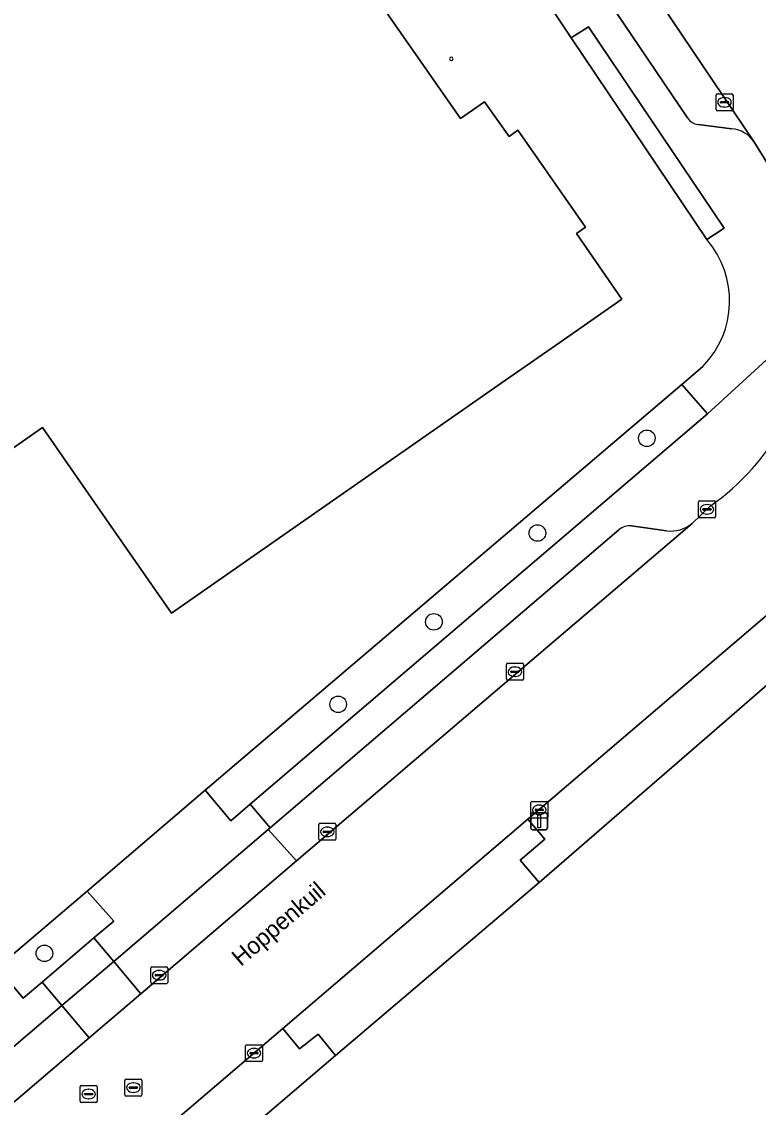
# Model space of a CAD drawing. Extents: x 156702 to 158052, y 387630 to 388992.
# Drawn here: x 157369.7 to 157413.2, y 387923.6 to 387987.6 of the extents above; entities that cross this region are included whole.
import ezdxf

# ---------------------------------------------------------------- set-up
doc = ezdxf.new("R2010")
doc.units = 0
for name, color, linetype in [('IMGEO_Boom', 7, 'Continuous'), ('IMGEO_Erf', 7, 'Continuous'), ('IMGEO_Groenvoorziening', 7, 'Continuous'), ('IMGEO_Kolk', 7, 'Continuous'), ('IMGEO_Lichtmast', 7, 'Continuous'), ('IMGEO_Openbare_ruimte_label', 7, 'Continuous'), ('IMGEO_Pand', 7, 'Continuous'), ('IMGEO_Parkeervlak_open', 7, 'Continuous'), ('IMGEO_Rijbaan_lokaal_gesloten', 7, 'Continuous'), ('IMGEO_Rijbaan_lokaal_open', 7, 'Continuous'), ('IMGEO_Rioolput', 7, 'Continuous'), ('IMGEO_Voetpad_open', 7, 'Continuous')]:
    doc.layers.add(name, color=color, linetype=linetype)

msp = doc.modelspace()

# ---------------------------------------------------------------- linework, layer by layer
at = {"layer": 'IMGEO_Boom'}
for centre in [(157406.636, 387963.06), (157400.18, 387957.47), (157394.069, 387952.231), (157388.42, 387947.363), (157371.085, 387932.67)]:
    msp.add_circle(centre, 0.489, dxfattribs=at)
at = {"layer": 'IMGEO_Erf'}
for points in [[(157387.19, 388039.182), (157396.502, 388024.511), (157402.741, 388015.343), (157403.363, 388015.762), (157413.667, 388000.525), (157419.496, 387991.988), (157429.376, 387977.195), (157434.667, 387969.272), (157436.067, 387967.176), (157433.406, 387964.883), (157433.59, 387964.667), (157433.73, 387964.762), (157434.042, 387964.343), (157428.255, 387959.385), (157427.905, 387959.765), (157428.127, 387959.953), (157427.939, 387960.171), (157427.645, 387960.512), (157423.765, 387957.199), (157400.278, 387936.844), (157388.261, 387926.646), (157368.779, 387910.004)], [(157410.18, 387974.784), (157402.177, 387986.679), (157401.025, 387988.392), (157393.215, 388000), (157371.506, 388032.159), (157369.928, 388034.292)], [(157368.332, 388003.627), (157376.541, 388009.329), (157383.04, 388000), (157393.139, 387985.505), (157395.632, 387981.926), (157397.057, 387982.917), (157398.504, 387980.872), (157399.026, 387981.234), (157403.012, 387975.51), (157402.494, 387975.151), (157405.159, 387971.263), (157401.506, 387968.719), (157398.499, 387966.625), (157378.578, 387952.75), (157377.05, 387954.95), (157374.897, 387958.052), (157370.981, 387963.692), (157367.677, 387961.4)], [(157380.576, 387942.295), (157408.698, 387966.241), (157409.937, 387967.305)], [(157342.068, 387909.735), (157348.404, 387915.137), (157358.974, 387923.885), (157368.291, 387931.841), (157373.604, 387936.342), (157380.576, 387942.295)]]:
    msp.add_lwpolyline(points, dxfattribs=at)
for centre, radius, start, end in [((157395.099, 387985.449), 0.1, 90, 270), ((157395.099, 387985.449), 0.1, 270, 90), ((157406.013, 387971.176), 5.512, 315.39208, 40.88604)]:
    msp.add_arc(centre, radius, start, end, dxfattribs=at)
at = {"layer": 'IMGEO_Groenvoorziening'}
for points in [[(157403.198, 387987.328), (157402.177, 387986.679), (157410.18, 387974.784), (157411.206, 387975.464)], [(157383.237, 387941.47), (157410.217, 387964.501), (157408.698, 387966.241), (157380.576, 387942.295), (157382.08, 387940.495)], [(157400.278, 387936.844), (157423.765, 387957.199), (157422.774, 387958.35), (157421.351, 387957.068), (157420.295, 387958.238), (157399.607, 387940.585), (157400.616, 387939.407), (157399.159, 387938.177)], [(157370.95, 387930.975), (157373.993, 387933.59), (157375.175, 387934.567), (157373.604, 387936.342), (157368.291, 387931.841), (157369.828, 387930.034)], [(157388.261, 387926.646), (157387.242, 387927.906), (157386.138, 387927.046), (157385.148, 387928.238), (157366.523, 387912.353), (157368.779, 387910.004)]]:
    msp.add_lwpolyline(points, close=True, dxfattribs=at)
at = {"layer": 'IMGEO_Kolk'}
for p, q in [((157410.719, 387982.461), (157410.719, 387983.313)), ((157410.794, 387983.387), (157411.646, 387983.387)), ((157411.72, 387983.313), (157411.72, 387982.461)), ((157410.978, 387982.881), (157410.978, 387982.893)), ((157411.416, 387982.844), (157411.018, 387982.844)), ((157411.021, 387982.93), (157411.419, 387982.93)), ((157411.207, 387983.167), (157411.232, 387983.167)), ((157411.462, 387982.893), (157411.462, 387982.881)), ((157411.646, 387982.387), (157410.794, 387982.387)), ((157411.23, 387982.607), (157411.205, 387982.607)), ((157409.683, 387958.441), (157409.683, 387959.293)), ((157409.758, 387959.367), (157410.61, 387959.367)), ((157410.171, 387959.147), (157410.196, 387959.147)), ((157410.684, 387959.293), (157410.684, 387958.441)), ((157410.61, 387958.367), (157409.758, 387958.367)), ((157409.942, 387958.861), (157409.942, 387958.873)), ((157410.38, 387958.824), (157409.982, 387958.824)), ((157409.985, 387958.91), (157410.383, 387958.91)), ((157410.194, 387958.587), (157410.169, 387958.587)), ((157410.426, 387958.873), (157410.426, 387958.861)), ((157398.349, 387948.86), (157398.349, 387949.712)), ((157398.424, 387949.786), (157399.276, 387949.786)), ((157398.651, 387949.329), (157399.049, 387949.329)), ((157398.837, 387949.566), (157398.862, 387949.566)), ((157399.35, 387949.712), (157399.35, 387948.86)), ((157399.276, 387948.786), (157398.424, 387948.786)), ((157398.608, 387949.28), (157398.608, 387949.292)), ((157399.046, 387949.243), (157398.648, 387949.243)), ((157398.86, 387949.006), (157398.835, 387949.006)), ((157399.092, 387949.292), (157399.092, 387949.28)), ((157399.86, 387941.637), (157400.712, 387941.637)), ((157399.785, 387940.711), (157399.785, 387941.563)), ((157400.044, 387941.131), (157400.044, 387941.143)), ((157400.482, 387941.094), (157400.084, 387941.094)), ((157400.087, 387941.18), (157400.485, 387941.18)), ((157400.273, 387941.417), (157400.298, 387941.417)), ((157400.528, 387941.143), (157400.528, 387941.131)), ((157400.786, 387941.563), (157400.786, 387940.711)), ((157387.354, 387940.342), (157388.206, 387940.342)), ((157400.712, 387940.637), (157399.86, 387940.637)), ((157400.296, 387940.857), (157400.271, 387940.857)), ((157387.279, 387939.416), (157387.279, 387940.268)), ((157387.538, 387939.836), (157387.538, 387939.848)), ((157387.976, 387939.799), (157387.578, 387939.799)), ((157387.581, 387939.885), (157387.979, 387939.885)), ((157387.767, 387940.122), (157387.792, 387940.122)), ((157388.022, 387939.848), (157388.022, 387939.836)), ((157388.28, 387940.268), (157388.28, 387939.416)), ((157388.206, 387939.342), (157387.354, 387939.342)), ((157387.79, 387939.562), (157387.765, 387939.562)), ((157377.36, 387930.954), (157377.36, 387931.806)), ((157377.435, 387931.88), (157378.287, 387931.88)), ((157377.619, 387931.374), (157377.619, 387931.386)), ((157377.662, 387931.423), (157378.06, 387931.423)), ((157377.848, 387931.66), (157377.873, 387931.66)), ((157378.103, 387931.386), (157378.103, 387931.374)), ((157378.361, 387931.806), (157378.361, 387930.954)), ((157378.287, 387930.88), (157377.435, 387930.88)), ((157378.057, 387931.337), (157377.659, 387931.337)), ((157377.871, 387931.1), (157377.846, 387931.1)), ((157382.954, 387926.355), (157382.954, 387927.207)), ((157383.029, 387927.281), (157383.881, 387927.281)), ((157383.442, 387927.061), (157383.467, 387927.061)), ((157383.955, 387927.207), (157383.955, 387926.355)), ((157383.881, 387926.281), (157383.029, 387926.281)), ((157383.213, 387926.775), (157383.213, 387926.787)), ((157383.651, 387926.738), (157383.253, 387926.738)), ((157383.256, 387926.824), (157383.654, 387926.824)), ((157383.465, 387926.501), (157383.44, 387926.501)), ((157383.697, 387926.787), (157383.697, 387926.775))]:
    msp.add_line(p, q, dxfattribs=at)
for points in [[(157410.719, 387982.461), (157410.719, 387983.313)], [(157410.794, 387983.387), (157411.646, 387983.387)], [(157411.72, 387983.313), (157411.72, 387982.461)], [(157411.646, 387982.387), (157410.794, 387982.387)], [(157409.683, 387958.441), (157409.683, 387959.293)], [(157409.758, 387959.367), (157410.61, 387959.367)], [(157410.684, 387959.293), (157410.684, 387958.441)], [(157410.61, 387958.367), (157409.758, 387958.367)], [(157398.349, 387948.86), (157398.349, 387949.712)], [(157398.424, 387949.786), (157399.276, 387949.786)], [(157399.35, 387949.712), (157399.35, 387948.86)], [(157399.276, 387948.786), (157398.424, 387948.786)], [(157399.86, 387941.637), (157400.712, 387941.637)], [(157399.785, 387940.711), (157399.785, 387941.563)], [(157400.786, 387941.563), (157400.786, 387940.711)], [(157387.354, 387940.342), (157388.206, 387940.342)], [(157400.712, 387940.637), (157399.86, 387940.637)], [(157387.279, 387939.416), (157387.279, 387940.268)], [(157388.28, 387940.268), (157388.28, 387939.416)], [(157388.206, 387939.342), (157387.354, 387939.342)], [(157377.36, 387930.954), (157377.36, 387931.806)], [(157377.435, 387931.88), (157378.287, 387931.88)], [(157378.361, 387931.806), (157378.361, 387930.954)], [(157378.287, 387930.88), (157377.435, 387930.88)], [(157382.954, 387926.355), (157382.954, 387927.207)], [(157383.029, 387927.281), (157383.881, 387927.281)], [(157383.955, 387927.207), (157383.955, 387926.355)], [(157383.881, 387926.281), (157383.029, 387926.281)]]:
    msp.add_lwpolyline(points, dxfattribs=at)
for centre, radius, start, end in [((157410.796, 387983.311), 0.0765, 91.55205, 178.44795), ((157410.796, 387983.311), 0.0765, 91.55205, 178.44795), ((157411.644, 387983.311), 0.0765, 1.55205, 88.44795), ((157411.644, 387983.311), 0.0765, 1.55205, 88.44795), ((157411.018, 387982.89), 0.0403, 85.87752, 175.75265), ((157411.015, 387982.88), 0.0366, 178.93798, 274.71019), ((157411.419, 387982.887), 0.043, 264.86636, 352.45326), ((157411.423, 387982.892), 0.0386, 1.73085, 96.63898), ((157410.796, 387982.463), 0.0765, 181.55205, 268.44795), ((157410.796, 387982.463), 0.0765, 181.55205, 268.44795), ((157411.644, 387982.463), 0.0765, 271.55205, 358.44795), ((157411.644, 387982.463), 0.0765, 271.55205, 358.44795), ((157409.76, 387959.291), 0.0765, 91.55205, 178.44795), ((157409.76, 387959.291), 0.0765, 91.55205, 178.44795), ((157410.608, 387959.291), 0.0765, 1.55205, 88.44795), ((157410.608, 387959.291), 0.0765, 1.55205, 88.44795), ((157409.76, 387958.443), 0.0765, 181.55205, 268.44795), ((157409.76, 387958.443), 0.0765, 181.55205, 268.44795), ((157409.982, 387958.87), 0.0403, 85.87752, 175.75265), ((157409.979, 387958.86), 0.0366, 178.93798, 274.71019), ((157410.383, 387958.867), 0.043, 264.86636, 352.45326), ((157410.387, 387958.872), 0.0386, 1.73085, 96.63898), ((157410.608, 387958.443), 0.0765, 271.55205, 358.44795), ((157410.608, 387958.443), 0.0765, 271.55205, 358.44795), ((157398.426, 387949.71), 0.0765, 91.55205, 178.44795), ((157398.426, 387949.71), 0.0765, 91.55205, 178.44795), ((157398.648, 387949.289), 0.0403, 85.87752, 175.75265), ((157399.053, 387949.291), 0.0386, 1.73085, 96.63898), ((157399.274, 387949.71), 0.0765, 1.55205, 88.44795), ((157399.274, 387949.71), 0.0765, 1.55205, 88.44795), ((157398.426, 387948.862), 0.0765, 181.55205, 268.44795), ((157398.426, 387948.862), 0.0765, 181.55205, 268.44795), ((157398.645, 387949.279), 0.0366, 178.93798, 274.71019), ((157399.049, 387949.286), 0.043, 264.86636, 352.45326), ((157399.274, 387948.862), 0.0765, 271.55205, 358.44795), ((157399.274, 387948.862), 0.0765, 271.55205, 358.44795), ((157399.862, 387941.561), 0.0765, 91.55205, 178.44795), ((157399.862, 387941.561), 0.0765, 91.55205, 178.44795), ((157400.71, 387941.561), 0.0765, 1.55205, 88.44795), ((157400.71, 387941.561), 0.0765, 1.55205, 88.44795), ((157400.084, 387941.14), 0.0403, 85.87752, 175.75265), ((157400.081, 387941.13), 0.0366, 178.93798, 274.71019), ((157400.485, 387941.137), 0.043, 264.86636, 352.45326), ((157400.489, 387941.142), 0.0386, 1.73085, 96.63898), ((157387.356, 387940.266), 0.0765, 91.55205, 178.44795), ((157387.356, 387940.266), 0.0765, 91.55205, 178.44795), ((157388.204, 387940.266), 0.0765, 1.55205, 88.44795), ((157388.204, 387940.266), 0.0765, 1.55205, 88.44795), ((157399.862, 387940.713), 0.0765, 181.55205, 268.44795), ((157399.862, 387940.713), 0.0765, 181.55205, 268.44795), ((157400.71, 387940.713), 0.0765, 271.55205, 358.44795), ((157400.71, 387940.713), 0.0765, 271.55205, 358.44795), ((157387.578, 387939.845), 0.0403, 85.87752, 175.75265), ((157387.575, 387939.835), 0.0366, 178.93798, 274.71019), ((157387.979, 387939.842), 0.043, 264.86636, 352.45326), ((157387.983, 387939.847), 0.0386, 1.73085, 96.63898), ((157387.356, 387939.418), 0.0765, 181.55205, 268.44795), ((157387.356, 387939.418), 0.0765, 181.55205, 268.44795), ((157388.204, 387939.418), 0.0765, 271.55205, 358.44795), ((157388.204, 387939.418), 0.0765, 271.55205, 358.44795), ((157377.437, 387931.804), 0.0765, 91.55205, 178.44795), ((157377.437, 387931.804), 0.0765, 91.55205, 178.44795), ((157377.659, 387931.383), 0.0403, 85.87752, 175.75265), ((157377.656, 387931.373), 0.0366, 178.93798, 274.71019), ((157378.06, 387931.38), 0.043, 264.86636, 352.45326), ((157378.064, 387931.385), 0.0386, 1.73085, 96.63898), ((157378.285, 387931.804), 0.0765, 1.55205, 88.44795), ((157378.285, 387931.804), 0.0765, 1.55205, 88.44795), ((157377.437, 387930.956), 0.0765, 181.55205, 268.44795), ((157377.437, 387930.956), 0.0765, 181.55205, 268.44795), ((157378.285, 387930.956), 0.0765, 271.55205, 358.44795), ((157378.285, 387930.956), 0.0765, 271.55205, 358.44795), ((157383.031, 387927.205), 0.0765, 91.55205, 178.44795), ((157383.031, 387927.205), 0.0765, 91.55205, 178.44795), ((157383.879, 387927.205), 0.0765, 1.55205, 88.44795), ((157383.879, 387927.205), 0.0765, 1.55205, 88.44795), ((157383.031, 387926.357), 0.0765, 181.55205, 268.44795), ((157383.031, 387926.357), 0.0765, 181.55205, 268.44795), ((157383.253, 387926.784), 0.0403, 85.87752, 175.75265), ((157383.25, 387926.774), 0.0366, 178.93798, 274.71019), ((157383.654, 387926.781), 0.043, 264.86636, 352.45326), ((157383.658, 387926.786), 0.0386, 1.73085, 96.63898), ((157383.879, 387926.357), 0.0765, 271.55205, 358.44795), ((157383.879, 387926.357), 0.0765, 271.55205, 358.44795)]:
    msp.add_arc(centre, radius, start, end, dxfattribs=at)
for centre, major_axis, ratio, start_param, end_param in [((157411.206, 387982.887), (-0.387, 0.002), 0.722429, 4.712389, 7.853982), ((157411.231, 387982.887), (-0.39, 0.002), 0.717154, 1.570796, 4.712389), ((157410.17, 387958.867), (-0.387, 0.002), 0.722429, 4.712389, 7.853982), ((157410.195, 387958.867), (-0.39, 0.002), 0.717154, 1.570796, 4.712389), ((157398.836, 387949.286), (-0.387, 0.002), 0.722429, 4.712389, 7.853982), ((157398.861, 387949.286), (-0.39, 0.002), 0.717154, 1.570796, 4.712389), ((157400.272, 387941.137), (-0.387, 0.002), 0.722429, 4.712389, 7.853982), ((157400.297, 387941.137), (-0.39, 0.002), 0.717154, 1.570796, 4.712389), ((157387.766, 387939.842), (-0.387, 0.002), 0.722429, 4.712389, 7.853982), ((157387.791, 387939.842), (-0.39, 0.002), 0.717154, 1.570796, 4.712389), ((157377.847, 387931.38), (-0.387, 0.002), 0.722429, 4.712389, 7.853982), ((157377.872, 387931.38), (-0.39, 0.002), 0.717154, 1.570796, 4.712389), ((157383.441, 387926.781), (-0.387, 0.002), 0.722429, 4.712389, 7.853982), ((157383.466, 387926.781), (-0.39, 0.002), 0.717154, 1.570796, 4.712389)]:
    msp.add_ellipse(centre, major_axis=major_axis, ratio=ratio, start_param=start_param, end_param=end_param, dxfattribs=at)
at = {"layer": 'IMGEO_Lichtmast'}
for p, q in [((157399.782, 387940.059), (157399.782, 387940.859)), ((157399.782, 387940.859), (157399.782, 387940.059)), ((157399.882, 387940.959), (157400.672, 387940.959)), ((157400.672, 387940.959), (157399.882, 387940.959)), ((157400.772, 387940.859), (157400.772, 387940.059)), ((157400.772, 387940.059), (157400.772, 387940.859)), ((157400.672, 387939.959), (157399.882, 387939.959)), ((157399.882, 387939.959), (157400.672, 387939.959))]:
    msp.add_line(p, q, dxfattribs=at)
msp.add_lwpolyline([(157400.202, 387940.834), (157400.352, 387940.834), (157400.352, 387940.084), (157400.202, 387940.084), (157400.202, 387940.834)], dxfattribs=at)
for centre, start, end in [((157399.882, 387940.859), 90, 180), ((157399.882, 387940.859), 90, 180), ((157400.672, 387940.859), 0, 90), ((157400.672, 387940.859), 360, 90), ((157399.882, 387940.059), 180, 270), ((157399.882, 387940.059), 180, 270), ((157400.672, 387940.059), 270, 0), ((157400.672, 387940.059), 270, 0)]:
    msp.add_arc(centre, 0.1, start, end, dxfattribs=at)
at = {"layer": 'IMGEO_Pand'}
msp.add_lwpolyline([(157367.677, 387961.4), (157370.981, 387963.692), (157374.897, 387958.052), (157377.05, 387954.95), (157378.578, 387952.75), (157398.499, 387966.625), (157401.506, 387968.719), (157405.159, 387971.263), (157402.494, 387975.151), (157403.012, 387975.51), (157399.026, 387981.234), (157398.504, 387980.872), (157397.057, 387982.917), (157395.632, 387981.926), (157393.139, 387985.505), (157383.04, 388000), (157376.541, 388009.329), (157368.332, 388003.627)], dxfattribs=at)
for start, end in [(90, 270), (270, 90)]:
    msp.add_arc((157395.099, 387985.449), 0.1, start, end, dxfattribs=at)
at = {"layer": 'IMGEO_Parkeervlak_open'}
for points in [[(157375.784, 388035.713), (157373.667, 388034.286), (157409.026, 387981.971)], [(157412.951, 387980.565), (157375.784, 388035.713)], [(157409.664, 387981.569), (157411.653, 387981.319)], [(157404.992, 387957.66), (157384.416, 387940.084), (157384.284, 387939.971), (157385.97, 387938.127), (157409.304, 387958.039)], [(157407.805, 387957.592), (157405.739, 387957.891)]]:
    msp.add_lwpolyline(points, dxfattribs=at)
msp.add_lwpolyline([(157376.781, 387930.287), (157375.173, 387932.192), (157372.115, 387929.588), (157373.736, 387927.688)], close=True, dxfattribs=at)
for centre, radius, start, end in [((157409.795, 387982.483), 0.924, 213.69458, 261.87585), ((157411.493, 387979.548), 1.778, 34.87515, 84.82078), ((157405.614, 387956.971), 0.928, 82.27315, 132.09394), ((157408.013, 387959.632), 2.05, 264.18178, 309.02726)]:
    msp.add_arc(centre, radius, start, end, dxfattribs=at)
at = {"layer": 'IMGEO_Rijbaan_lokaal_gesloten'}
for points in [[(157375.701, 388035.836), (157375.784, 388035.713), (157412.951, 387980.565), (157414.43, 387978.195), (157420.098, 387982.532), (157416.586, 387987.739), (157407.925, 388000.59), (157400.555, 388011.557), (157392.527, 388023.508), (157380.459, 388041.129), (157377.848, 388044.562)], [(157410.375, 387959.057), (157409.304, 387958.039), (157385.97, 387938.127), (157376.781, 387930.287), (157373.736, 387927.688), (157362.226, 387917.866), (157353.99, 387910.839), (157345.4, 387903.508), (157345.224, 387903.358)], [(157348.557, 387896.99), (157366.11, 387912.001), (157366.523, 387912.353), (157385.148, 387928.238), (157399.607, 387940.585), (157420.295, 387958.238), (157421.577, 387959.313)]]:
    msp.add_lwpolyline(points, dxfattribs=at)
msp.add_arc((157402.136, 387970.801), 14.346, 305.05343, 357.72062, dxfattribs=at)
at = {"layer": 'IMGEO_Rijbaan_lokaal_open'}
msp.add_lwpolyline([(157388.261, 387926.646), (157400.278, 387936.844), (157399.159, 387938.177), (157400.616, 387939.407), (157399.607, 387940.585), (157385.148, 387928.238), (157386.138, 387927.046), (157387.242, 387927.906)], close=True, dxfattribs=at)
at = {"layer": 'IMGEO_Rioolput'}
for p, q in [((157375.838, 387924.321), (157375.838, 387925.173)), ((157375.913, 387925.247), (157376.765, 387925.247)), ((157376.326, 387925.027), (157376.351, 387925.027)), ((157376.839, 387925.173), (157376.839, 387924.321)), ((157373.199, 387923.942), (157373.199, 387924.794)), ((157373.274, 387924.868), (157374.126, 387924.868)), ((157373.458, 387924.362), (157373.458, 387924.374)), ((157373.501, 387924.411), (157373.899, 387924.411)), ((157373.687, 387924.648), (157373.712, 387924.648)), ((157373.942, 387924.374), (157373.942, 387924.362)), ((157374.2, 387924.794), (157374.2, 387923.942)), ((157376.097, 387924.741), (157376.097, 387924.753)), ((157376.535, 387924.704), (157376.137, 387924.704)), ((157376.14, 387924.79), (157376.538, 387924.79)), ((157376.349, 387924.467), (157376.324, 387924.467)), ((157376.581, 387924.753), (157376.581, 387924.741)), ((157374.126, 387923.868), (157373.274, 387923.868)), ((157373.896, 387924.325), (157373.498, 387924.325)), ((157373.71, 387924.088), (157373.685, 387924.088)), ((157376.765, 387924.247), (157375.913, 387924.247))]:
    msp.add_line(p, q, dxfattribs=at)
for points in [[(157375.838, 387924.321), (157375.838, 387925.173)], [(157375.913, 387925.247), (157376.765, 387925.247)], [(157376.839, 387925.173), (157376.839, 387924.321)], [(157373.199, 387923.942), (157373.199, 387924.794)], [(157373.274, 387924.868), (157374.126, 387924.868)], [(157374.2, 387924.794), (157374.2, 387923.942)], [(157374.126, 387923.868), (157373.274, 387923.868)], [(157376.765, 387924.247), (157375.913, 387924.247)]]:
    msp.add_lwpolyline(points, dxfattribs=at)
for centre, radius, start, end in [((157375.915, 387925.171), 0.0765, 91.55205, 178.44795), ((157375.915, 387925.171), 0.0765, 91.55205, 178.44795), ((157376.763, 387925.171), 0.0765, 1.55205, 88.44795), ((157376.763, 387925.171), 0.0765, 1.55205, 88.44795), ((157373.276, 387924.792), 0.0765, 91.55205, 178.44795), ((157373.276, 387924.792), 0.0765, 91.55205, 178.44795), ((157373.498, 387924.371), 0.0403, 85.87752, 175.75265), ((157373.495, 387924.361), 0.0366, 178.93798, 274.71019), ((157373.899, 387924.368), 0.043, 264.86636, 352.45326), ((157373.903, 387924.373), 0.0386, 1.73085, 96.63898), ((157374.124, 387924.792), 0.0765, 1.55205, 88.44795), ((157374.124, 387924.792), 0.0765, 1.55205, 88.44795), ((157376.137, 387924.75), 0.0403, 85.87752, 175.75265), ((157376.134, 387924.74), 0.0366, 178.93798, 274.71019), ((157376.538, 387924.747), 0.043, 264.86636, 352.45326), ((157376.542, 387924.752), 0.0386, 1.73085, 96.63898), ((157373.276, 387923.944), 0.0765, 181.55205, 268.44795), ((157373.276, 387923.944), 0.0765, 181.55205, 268.44795), ((157374.124, 387923.944), 0.0765, 271.55205, 358.44795), ((157374.124, 387923.944), 0.0765, 271.55205, 358.44795), ((157375.915, 387924.323), 0.0765, 181.55205, 268.44795), ((157375.915, 387924.323), 0.0765, 181.55205, 268.44795), ((157376.763, 387924.323), 0.0765, 271.55205, 358.44795), ((157376.763, 387924.323), 0.0765, 271.55205, 358.44795)]:
    msp.add_arc(centre, radius, start, end, dxfattribs=at)
for centre, major_axis, ratio, start_param, end_param in [((157376.325, 387924.747), (-0.387, 0.002), 0.722429, 4.712389, 7.853982), ((157376.35, 387924.747), (-0.39, 0.002), 0.717154, 1.570796, 4.712389), ((157373.686, 387924.368), (-0.387, 0.002), 0.722429, 4.712389, 7.853982), ((157373.711, 387924.368), (-0.39, 0.002), 0.717154, 1.570796, 4.712389)]:
    msp.add_ellipse(centre, major_axis=major_axis, ratio=ratio, start_param=start_param, end_param=end_param, dxfattribs=at)
at = {"layer": 'IMGEO_Voetpad_open'}
for points in [[(157409.026, 387981.971), (157373.667, 388034.286), (157373.583, 388034.411), (157372.113, 388033.384), (157402.016, 387989.08), (157401.025, 387988.392), (157402.177, 387986.679), (157403.198, 387987.328), (157411.206, 387975.464), (157410.18, 387974.784)], [(157411.653, 387981.319), (157409.664, 387981.569)], [(157414.43, 387978.195), (157412.951, 387980.565)], [(157416.47, 387970.23), (157410.217, 387964.501), (157383.237, 387941.47), (157384.416, 387940.084), (157404.992, 387957.66)], [(157409.937, 387967.305), (157408.698, 387966.241), (157410.217, 387964.501), (157416.47, 387970.23)], [(157409.304, 387958.039), (157410.375, 387959.057)], [(157405.739, 387957.891), (157407.805, 387957.592)]]:
    msp.add_lwpolyline(points, dxfattribs=at)
for points in [[(157384.284, 387939.971), (157384.416, 387940.084), (157383.237, 387941.47), (157382.08, 387940.495), (157380.576, 387942.295), (157373.604, 387936.342), (157375.175, 387934.567), (157373.993, 387933.59), (157375.173, 387932.192)], [(157385.97, 387938.127), (157384.284, 387939.971), (157375.173, 387932.192), (157376.781, 387930.287)], [(157373.993, 387933.59), (157370.95, 387930.975), (157372.115, 387929.588), (157375.173, 387932.192)], [(157358.974, 387923.885), (157360.548, 387922.073), (157359.402, 387921.146), (157360.599, 387919.773), (157372.115, 387929.588), (157370.95, 387930.975), (157369.828, 387930.034), (157368.291, 387931.841)], [(157373.736, 387927.688), (157372.115, 387929.588), (157360.599, 387919.773), (157362.226, 387917.866)]]:
    msp.add_lwpolyline(points, close=True, dxfattribs=at)
for centre, radius, start, end in [((157409.795, 387982.483), 0.924, 213.69458, 261.87585), ((157411.493, 387979.548), 1.778, 34.87515, 84.82078), ((157406.013, 387971.176), 5.512, 315.39208, 40.88604), ((157402.136, 387970.801), 14.346, 305.05343, 357.72062), ((157405.614, 387956.971), 0.928, 82.27315, 132.09394), ((157408.013, 387959.632), 2.05, 264.18178, 309.02726)]:
    msp.add_arc(centre, radius, start, end, dxfattribs=at)

# ---------------------------------------------------------------- texts
at = {"layer": 'IMGEO_Openbare_ruimte_label'}
msp.add_text('Hoppenkuil', height=1, rotation=40.45838, dxfattribs=at).set_placement((157382.676, 387931.863))

doc.saveas('drawing.dxf')
